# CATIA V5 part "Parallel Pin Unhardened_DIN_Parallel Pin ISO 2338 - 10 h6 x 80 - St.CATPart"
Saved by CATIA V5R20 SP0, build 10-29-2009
Part number: Parallel Pin Unhardened_DIN_Parallel Pin ISO 2338 - 10 h6 x 80 - St
Revision: ANY
Definition: UNKNOWN
Nomenclature: Parallel Pin Unhardened_DIN_Parallel Pin ISO 2338 - 10 h6 x 80 - St
Source: Unknown
Bounding box of the stored display mesh (mm): x 0 to 80, y -5 to 5, z -5 to 5
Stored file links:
  C:\Users\Utente\Desktop\IO LAVORO\3D X SITO CF\CUMSA\3D files SD\SD 3220\Parallel Pin Unhardened_DIN_Parallel Pin ISO 2338 - 10 h6 x 80 - St.CATPart
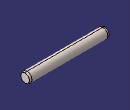
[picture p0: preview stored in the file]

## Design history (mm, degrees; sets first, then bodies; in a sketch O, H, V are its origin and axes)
Body1 "Base-Revolve" (main body)
  Solid1: solid without history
